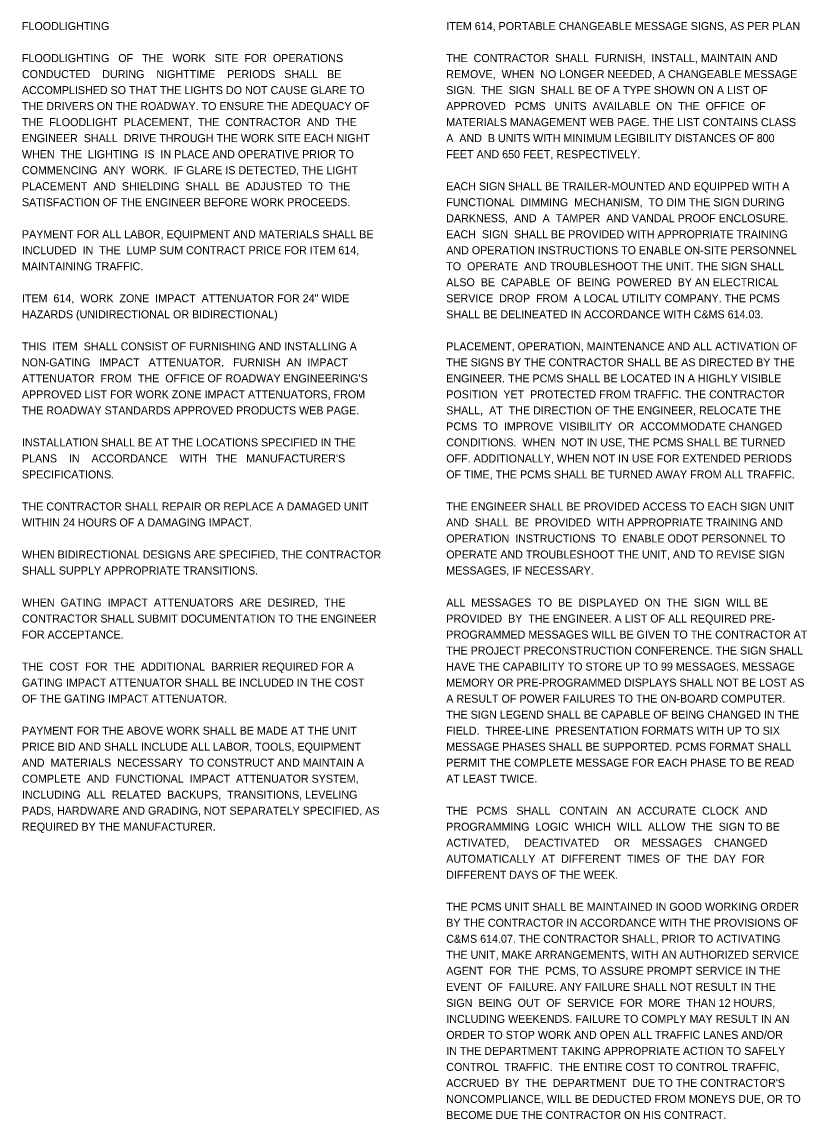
# Model space of a CAD drawing. Extents: x -31.1 to 65.6, y 0 to 22.
# Drawn here: x -31.1 to -17.37, y 1.96 to 21.14 of the extents above; entities that cross this region are included whole.
import ezdxf

# ---------------------------------------------------------------- set-up
doc = ezdxf.new("R2010")
doc.units = 0
doc.layers.add('SH_Text', color=7, linetype='Continuous')
doc.layers.add('TX_P_1', color=7, linetype='Continuous')

msp = doc.modelspace()

# ---------------------------------------------------------------- texts
at = {"layer": 'SH_Text'}
for s, p in [('ITEM 614, PORTABLE CHANGEABLE MESSAGE SIGNS, AS PER PLAN', (-23.68, 21)), ('THE  CONTRACTOR  SHALL  FURNISH,  INSTALL, MAINTAIN AND', (-23.68, 20.44)), ('REMOVE,  WHEN  NO LONGER NEEDED, A CHANGEABLE MESSAGE', (-23.68, 20.16)), ('SIGN.  THE  SIGN  SHALL BE OF A TYPE SHOWN ON A LIST OF', (-23.68, 19.88)), ('APPROVED   PCMS   UNITS  AVAILABLE  ON  THE  OFFICE  OF', (-23.68, 19.6)), ('MATERIALS MANAGEMENT WEB PAGE. THE LIST CONTAINS CLASS', (-23.68, 19.32)), ('A  AND  B UNITS WITH MINIMUM LEGIBILITY DISTANCES OF 800', (-23.68, 19.04)), ('FEET AND 650 FEET, RESPECTIVELY.', (-23.68, 18.76)), ('EACH SIGN SHALL BE TRAILER-MOUNTED AND EQUIPPED WITH A', (-23.68, 18.2)), ('FUNCTIONAL  DIMMING  MECHANISM,  TO DIM THE SIGN DURING', (-23.68, 17.92)), ('DARKNESS,  AND  A  TAMPER  AND VANDAL PROOF ENCLOSURE.', (-23.68, 17.64)), ('EACH  SIGN  SHALL BE PROVIDED WITH APPROPRIATE TRAINING', (-23.68, 17.36)), ('AND OPERATION INSTRUCTIONS TO ENABLE ON-SITE PERSONNEL', (-23.68, 17.08)), ('TO  OPERATE  AND TROUBLESHOOT THE UNIT. THE SIGN SHALL', (-23.68, 16.8)), ('ALSO  BE  CAPABLE  OF  BEING  POWERED  BY AN ELECTRICAL', (-23.68, 16.52)), ('SERVICE  DROP  FROM  A LOCAL UTILITY COMPANY. THE PCMS', (-23.68, 16.24)), ('SHALL BE DELINEATED IN ACCORDANCE WITH C&MS 614.03.', (-23.68, 15.96)), ('PLACEMENT, OPERATION, MAINTENANCE AND ALL ACTIVATION OF', (-23.68, 15.4)), ('THE SIGNS BY THE CONTRACTOR SHALL BE AS DIRECTED BY THE', (-23.68, 15.12)), ('ENGINEER. THE PCMS SHALL BE LOCATED IN A HIGHLY VISIBLE', (-23.68, 14.84)), ('POSITION  YET  PROTECTED FROM TRAFFIC. THE CONTRACTOR', (-23.68, 14.56)), ('SHALL,  AT  THE DIRECTION OF THE ENGINEER, RELOCATE THE', (-23.68, 14.28)), ('PCMS  TO  IMPROVE  VISIBILITY  OR  ACCOMMODATE CHANGED', (-23.68, 14)), ('CONDITIONS.  WHEN  NOT IN USE, THE PCMS SHALL BE TURNED', (-23.68, 13.72)), ('OFF. ADDITIONALLY, WHEN NOT IN USE FOR EXTENDED PERIODS', (-23.68, 13.44)), ('OF TIME, THE PCMS SHALL BE TURNED AWAY FROM ALL TRAFFIC.', (-23.68, 13.16)), ('THE ENGINEER SHALL BE PROVIDED ACCESS TO EACH SIGN UNIT', (-23.68, 12.6)), ('AND  SHALL  BE  PROVIDED  WITH APPROPRIATE TRAINING AND', (-23.68, 12.32)), ('OPERATION  INSTRUCTIONS  TO  ENABLE ODOT PERSONNEL TO', (-23.68, 12.04)), ('OPERATE AND TROUBLESHOOT THE UNIT, AND TO REVISE SIGN', (-23.68, 11.76)), ('MESSAGES, IF NECESSARY.', (-23.68, 11.48)), ('ALL  MESSAGES  TO  BE  DISPLAYED  ON  THE  SIGN  WILL BE', (-23.68, 10.92)), ('PROVIDED  BY  THE ENGINEER. A LIST OF ALL REQUIRED PRE-', (-23.68, 10.64)), ('PROGRAMMED MESSAGES WILL BE GIVEN TO THE CONTRACTOR AT', (-23.68, 10.36)), ('THE PROJECT PRECONSTRUCTION CONFERENCE. THE SIGN SHALL', (-23.68, 10.08)), ('HAVE THE CAPABILITY TO STORE UP TO 99 MESSAGES. MESSAGE', (-23.68, 9.8)), ('MEMORY OR PRE-PROGRAMMED DISPLAYS SHALL NOT BE LOST AS', (-23.68, 9.52)), ('A RESULT OF POWER FAILURES TO THE ON-BOARD COMPUTER.', (-23.68, 9.24)), ('THE SIGN LEGEND SHALL BE CAPABLE OF BEING CHANGED IN THE', (-23.68, 8.96)), ('FIELD.  THREE-LINE  PRESENTATION FORMATS WITH UP TO SIX', (-23.68, 8.68)), ('MESSAGE PHASES SHALL BE SUPPORTED. PCMS FORMAT SHALL', (-23.68, 8.4)), ('PERMIT THE COMPLETE MESSAGE FOR EACH PHASE TO BE READ', (-23.68, 8.12)), ('AT LEAST TWICE.', (-23.68, 7.84)), ('THE   PCMS   SHALL   CONTAIN   AN  ACCURATE  CLOCK  AND', (-23.68, 7.28)), ('PROGRAMMING  LOGIC  WHICH  WILL  ALLOW  THE  SIGN TO BE', (-23.68, 7)), ('ACTIVATED,     DEACTIVATED     OR    MESSAGES    CHANGED', (-23.68, 6.72)), ('AUTOMATICALLY  AT  DIFFERENT  TIMES  OF  THE  DAY  FOR', (-23.68, 6.44)), ('DIFFERENT DAYS OF THE WEEK.', (-23.68, 6.16)), ('THE PCMS UNIT SHALL BE MAINTAINED IN GOOD WORKING ORDER', (-23.68, 5.6)), ('BY THE CONTRACTOR IN ACCORDANCE WITH THE PROVISIONS OF', (-23.68, 5.32)), ('C&MS 614.07. THE CONTRACTOR SHALL, PRIOR TO ACTIVATING', (-23.68, 5.04)), ('THE UNIT, MAKE ARRANGEMENTS, WITH AN AUTHORIZED SERVICE', (-23.68, 4.76)), ('AGENT  FOR  THE  PCMS, TO ASSURE PROMPT SERVICE IN THE', (-23.68, 4.48)), ('EVENT  OF  FAILURE. ANY FAILURE SHALL NOT RESULT IN THE', (-23.68, 4.2)), ('SIGN  BEING  OUT  OF  SERVICE  FOR  MORE  THAN 12 HOURS,', (-23.68, 3.92)), ('INCLUDING WEEKENDS. FAILURE TO COMPLY MAY RESULT IN AN', (-23.68, 3.64)), ('ORDER TO STOP WORK AND OPEN ALL TRAFFIC LANES AND/OR', (-23.68, 3.36)), ('IN THE DEPARTMENT TAKING APPROPRIATE ACTION TO SAFELY', (-23.68, 3.08)), ('CONTROL  TRAFFIC.  THE ENTIRE COST TO CONTROL TRAFFIC,', (-23.68, 2.8)), ("ACCRUED  BY  THE  DEPARTMENT  DUE TO THE CONTRACTOR'S", (-23.68, 2.52)), ('NONCOMPLIANCE, WILL BE DEDUCTED FROM MONEYS DUE, OR TO', (-23.68, 2.24)), ('BECOME DUE THE CONTRACTOR ON HIS CONTRACT.', (-23.68, 1.96))]:
    msp.add_text(s, height=0.14, dxfattribs=at).set_placement(p)
at = {"layer": 'TX_P_1'}
for s, p in [('FLOODLIGHTING', (-31.1, 21)), ('FLOODLIGHTING   OF   THE   WORK   SITE  FOR  OPERATIONS', (-31.1, 20.44)), ('CONDUCTED    DURING    NIGHTTIME    PERIODS   SHALL   BE', (-31.1, 20.16)), ('ACCOMPLISHED SO THAT THE LIGHTS DO NOT CAUSE GLARE TO', (-31.1, 19.88)), ('THE DRIVERS ON THE ROADWAY. TO ENSURE THE ADEQUACY OF', (-31.1, 19.6)), ('THE  FLOODLIGHT  PLACEMENT,  THE  CONTRACTOR  AND  THE', (-31.1, 19.32)), ('ENGINEER  SHALL  DRIVE THROUGH THE WORK SITE EACH NIGHT', (-31.1, 19.04)), ('WHEN  THE  LIGHTING  IS  IN PLACE AND OPERATIVE PRIOR TO', (-31.1, 18.76)), ('COMMENCING  ANY  WORK.  IF GLARE IS DETECTED, THE LIGHT', (-31.1, 18.48)), ('PLACEMENT  AND  SHIELDING  SHALL  BE  ADJUSTED  TO  THE', (-31.1, 18.2)), ('SATISFACTION OF THE ENGINEER BEFORE WORK PROCEEDS.', (-31.1, 17.92)), ('PAYMENT FOR ALL LABOR, EQUIPMENT AND MATERIALS SHALL BE', (-31.1, 17.36)), ('INCLUDED  IN  THE  LUMP SUM CONTRACT PRICE FOR ITEM 614,', (-31.1, 17.08)), ('MAINTAINING TRAFFIC.', (-31.1, 16.8)), ('ITEM  614,  WORK  ZONE  IMPACT  ATTENUATOR FOR 24" WIDE', (-31.1, 16.24)), ('HAZARDS (UNIDIRECTIONAL OR BIDIRECTIONAL)', (-31.1, 15.96)), ('THIS  ITEM  SHALL CONSIST OF FURNISHING AND INSTALLING A', (-31.1, 15.4)), ('NON-GATING   IMPACT   ATTENUATOR.   FURNISH  AN  IMPACT', (-31.1, 15.12)), ("ATTENUATOR  FROM  THE  OFFICE OF ROADWAY ENGINEERING'S", (-31.1, 14.84)), ('APPROVED LIST FOR WORK ZONE IMPACT ATTENUATORS, FROM', (-31.1, 14.56)), ('THE ROADWAY STANDARDS APPROVED PRODUCTS WEB PAGE.', (-31.1, 14.28)), ('INSTALLATION SHALL BE AT THE LOCATIONS SPECIFIED IN THE', (-31.1, 13.72)), ("PLANS    IN    ACCORDANCE    WITH   THE   MANUFACTURER'S", (-31.1, 13.44)), ('SPECIFICATIONS.', (-31.1, 13.16)), ('THE CONTRACTOR SHALL REPAIR OR REPLACE A DAMAGED UNIT', (-31.1, 12.6)), ('WITHIN 24 HOURS OF A DAMAGING IMPACT.', (-31.1, 12.32)), ('WHEN BIDIRECTIONAL DESIGNS ARE SPECIFIED, THE CONTRACTOR', (-31.1, 11.76)), ('SHALL SUPPLY APPROPRIATE TRANSITIONS.', (-31.1, 11.48)), ('WHEN  GATING  IMPACT  ATTENUATORS  ARE  DESIRED,  THE', (-31.1, 10.92)), ('CONTRACTOR SHALL SUBMIT DOCUMENTATION TO THE ENGINEER', (-31.1, 10.64)), ('FOR ACCEPTANCE.', (-31.1, 10.36)), ('THE  COST  FOR  THE  ADDITIONAL  BARRIER REQUIRED FOR A', (-31.1, 9.8)), ('GATING IMPACT ATTENUATOR SHALL BE INCLUDED IN THE COST', (-31.1, 9.52)), ('OF THE GATING IMPACT ATTENUATOR.', (-31.1, 9.24)), ('PAYMENT FOR THE ABOVE WORK SHALL BE MADE AT THE UNIT', (-31.1, 8.68)), ('PRICE BID AND SHALL INCLUDE ALL LABOR, TOOLS, EQUIPMENT', (-31.1, 8.4)), ('AND  MATERIALS  NECESSARY  TO CONSTRUCT AND MAINTAIN A', (-31.1, 8.12)), ('COMPLETE  AND  FUNCTIONAL  IMPACT  ATTENUATOR SYSTEM,', (-31.1, 7.84)), ('INCLUDING  ALL  RELATED  BACKUPS,  TRANSITIONS, LEVELING', (-31.1, 7.56)), ('PADS, HARDWARE AND GRADING, NOT SEPARATELY SPECIFIED, AS', (-31.1, 7.28)), ('REQUIRED BY THE MANUFACTURER.', (-31.1, 7))]:
    msp.add_text(s, height=0.14, dxfattribs=at).set_placement(p)

doc.saveas('drawing.dxf')
